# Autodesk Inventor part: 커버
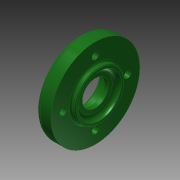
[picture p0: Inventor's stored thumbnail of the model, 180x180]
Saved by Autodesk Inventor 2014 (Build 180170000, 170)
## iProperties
Created: 2015-11
Part Number: 커버
Material: 알루미늄 6061
Document SubType Name: Modeling
Designer: mduedu
Density: 2.71 g/cm^3
Mass: 57.8273 g
Surface Area: 81.1807 cm^2
Volume: 21.3385 cm^3
Appearance: 매끄러움 - 짙은 산림 녹색
Author: mduedu
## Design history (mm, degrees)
sketch "스케치1"
  geometry: L1 (-6.5, 0)-(6.5, 0); L2 (-6.5, 0)-(-6.5, 29); L3 (-6.5, 29)-(3.5, 29); L4 (3.5, 29)-(3.5, 16); L5 (3.5, 16)-(6.5, 16); L6 (6.5, 16)-(6.5, 0); 2 further points
  constraints: 12 end point, 3 perpendicular, 2 parallel, 1 coincident, 1 horizontal, 1 midpoint
  dimensions: "d0" = 13 distance of L1.start L1.end; "d1" = 58 diameter of L3 L1; "d2" = 3 distance of L4.end L5.end; "d3" = 32 diameter of L5 L1
revolve "회전1" sketch "스케치1" stored, may be unused: angle "d4" = 90 deg
hole "구멍1" diameter "d7" = 28; stored, may be unused: countersink angle "d11" = 90 deg, drill point angle "d13" = 0 deg; dims "d8" = 6, "d9" = 4, "d10" = 2, "d12" = 3, "d65" = 10, "d66" = 10
hole "구멍2" diameter "d16" = 25; stored, may be unused: countersink angle "d20" = 90 deg, drill point angle "d22" = 0 deg; dims "d17" = 6, "d18" = 4, "d19" = 2, "d21" = 7.3, "d67" = 10, "d68" = 10
hole "구멍3" diameter "d25" = 17; stored, may be unused: countersink angle "d29" = 90 deg, drill point angle "d31" = 0 deg; dims "d23" = 10, "d24" = 10, "d26" = 6, "d27" = 4, "d28" = 2, "d30" = 4.2
chamfer "모따기1" distance "d32" = 0.7; stored, may be unused: second distance "d33" = 2, angle "d34" = 30 deg
fillet "모깎기1" dims "d35" = 0.2
fillet "모깎기2" dims "d36" = 3
fillet "모깎기3" dims "d37" = 3
fillet "모깎기4" dims "d38" = 1
sketch "스케치3" dims "d61" = 42
  geometry: C1 r 29 at (0, 0) reference; 2 further points
  constraints: 2 vertical alignment, 1 coincident, 2 other
hole "구멍4" sketch "스케치3" at (0, -21) diameter "d44" = 4.5; stored, may be unused: countersink angle "d48" = 90 deg, drill point angle "d50" = 0 deg; dims "d45" = 6, "d46" = 8, "d47" = 4.6, "d49" = 8
chamfer "모따기2" distance "d62" = 0.5; stored, may be unused: second distance "d63" = 2, angle "d64" = 45 deg
node "솔리드1"
pattern_circular "원형 패턴1" dims angle "d54" = 360 deg
